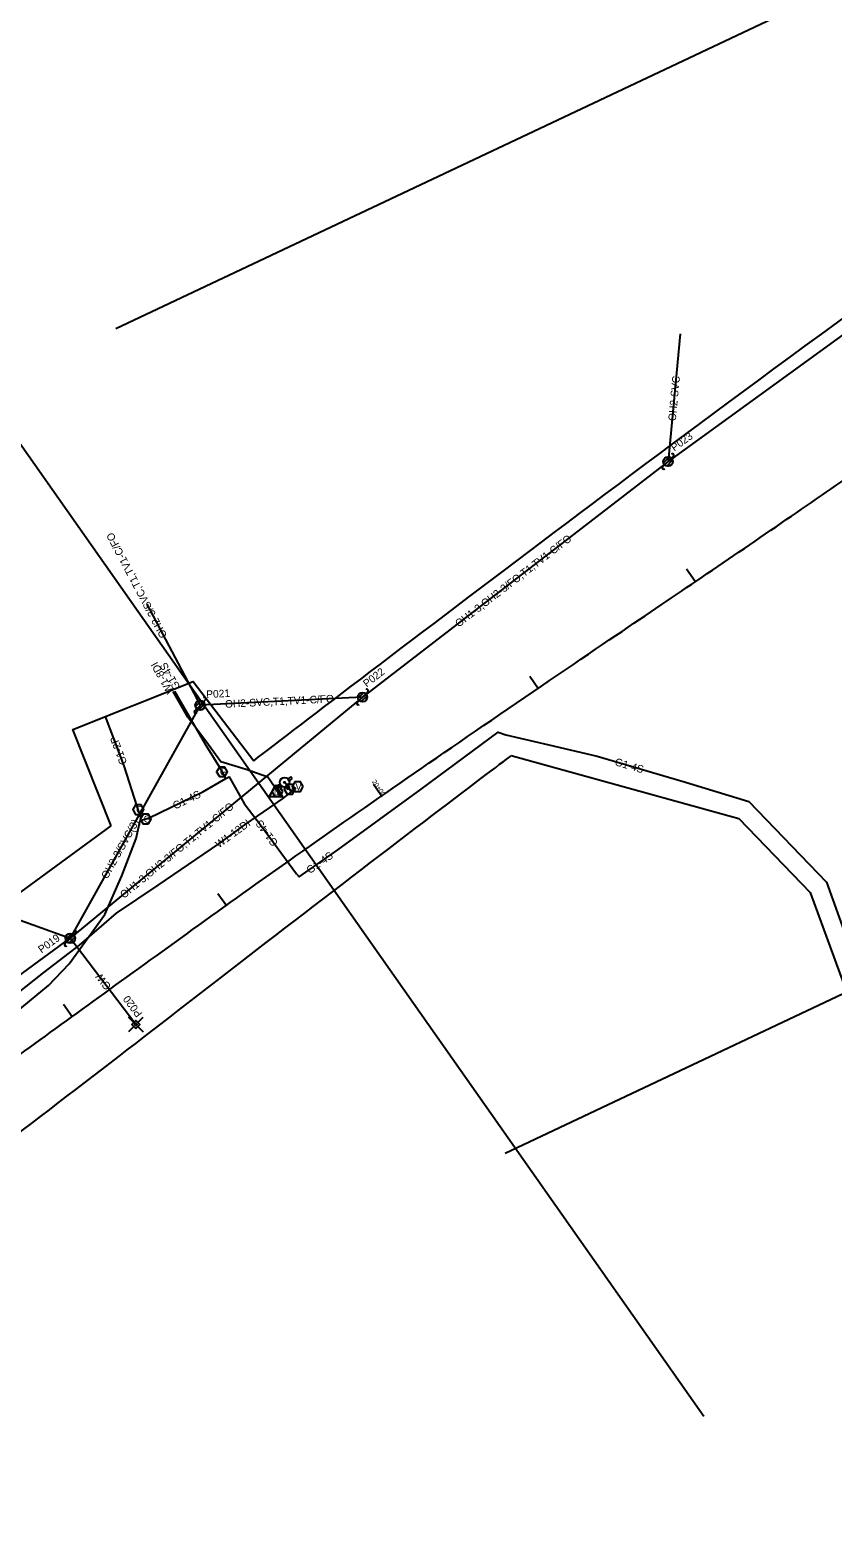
# Model space of a CAD drawing. Extents: x 1991878 to 2008544, y 770238 to 1141211.
# Drawn here: x 2004550 to 2004972, y 1139018 to 1139811 of the extents above; entities that cross this region are included whole.
import ezdxf

# ---------------------------------------------------------------- set-up
doc = ezdxf.new("R2010")
doc.units = 0
for name, color, linetype in [('RD_EX_SU_Gas', 7, 'Continuous'), ('RD_EX_SU_H2O', 7, 'Continuous'), ('RD_EX_SU_Misc', 7, 'Continuous'), ('RD_EX_SU_Ovhd', 7, 'Continuous'), ('RD_EX_SU_Pole', 7, 'Continuous'), ('RD_EX_SU_SwpLmt', 7, 'Continuous'), ('RD_EX_SU_TX_Gas', 7, 'Continuous'), ('RD_EX_SU_TX_H2O', 7, 'Continuous'), ('RD_EX_SU_TX_Ovhd', 7, 'Continuous'), ('RD_EX_SU_TX_Pole', 7, 'Continuous'), ('RD_HC_Cl', 7, 'Continuous')]:
    doc.layers.add(name, color=color, linetype=linetype)

msp = doc.modelspace()

# ---------------------------------------------------------------- linework, layer by layer
at = {"layer": 'RD_EX_SU_Gas'}
for points in [[(2004127.39, 1138992.43), (2004167.83, 1139021.75), (2004208.7, 1139051.33), (2004249.23, 1139080.61), (2004289.2, 1139109.77), (2004329.8, 1139139.24), (2004370.29, 1139168.18), (2004410.8, 1139197.77), (2004451.13, 1139226.8), (2004491.65, 1139256.41), (2004532.34, 1139286.17), (2004559.51, 1139308.55), (2004570.45, 1139319.96), (2004589.25, 1139345.84), (2004598.18, 1139366.3), (2004605.75, 1139385.94), (2004607.89, 1139395.38), (2004612.64, 1139396.79), (2004640.85, 1139410.39), (2004653.01, 1139417.54), (2004650.63, 1139421.79), (2004642.64, 1139434.89), (2004626.13, 1139463.52)], [(2004608.45, 1139396.57), (2004606.18, 1139402.73), (2004599.47, 1139424.1), (2004589.65, 1139450.12)], [(2004653.01, 1139417.54), (2004654.65, 1139418.3), (2004662.64, 1139404.34), (2004671.73, 1139392.42), (2004690.15, 1139367.32), (2004691.56, 1139365.69), (2004711.89, 1139379.94), (2004755.77, 1139411.93), (2004796.21, 1139441.85), (2004800.33, 1139440.53), (2004823.01, 1139435.16), (2004848.41, 1139429.24), (2004894.92, 1139415.6), (2004928.18, 1139405.32), (2004969.16, 1139362.83), (2004982.49, 1139325.73), (2004996.03, 1139288.62), (2005016.28, 1139234.18), (2005017.5, 1139230.57)]]:
    msp.add_lwpolyline(points, dxfattribs=at)
for points in [[(2004652.4, 1139418.48), (2004653.84, 1139420.98), (2004652.4, 1139423.48), (2004649.51, 1139423.48), (2004648.07, 1139420.98), (2004649.51, 1139418.48)], [(2004608.33, 1139398.59), (2004609.77, 1139401.09), (2004608.33, 1139403.59), (2004605.44, 1139403.59), (2004604, 1139401.09), (2004605.44, 1139398.59)], [(2004612.24, 1139393.64), (2004613.68, 1139396.14), (2004612.24, 1139398.64), (2004609.35, 1139398.64), (2004607.91, 1139396.14), (2004609.35, 1139393.64)]]:
    msp.add_lwpolyline(points, close=True, dxfattribs=at)
at = {"layer": 'RD_EX_SU_H2O'}
for p, q in [((2004687.17, 1139418.36), (2004685.58, 1139417.29)), ((2004686.24, 1139416.22), (2004687.87, 1139417.31)), ((2004687.87, 1139417.31), (2004687.17, 1139418.36)), ((2004681.49, 1139414.54), (2004679.85, 1139413.44)), ((2004679.85, 1139413.44), (2004680.55, 1139412.39)), ((2004680.55, 1139412.39), (2004682.24, 1139413.52)), ((2004684.62, 1139413.08), (2004685.53, 1139411.72)), ((2004685.53, 1139411.72), (2004686.58, 1139412.42)), ((2004686.58, 1139412.42), (2004685.68, 1139413.76))]:
    msp.add_line(p, q, dxfattribs=at)
for points in [[(2004682.25, 1139407.48), (2004678.5, 1139413.01), (2004675.07, 1139418.12), (2004663.58, 1139422.21), (2004650.35, 1139426.3), (2004643.87, 1139435.2), (2004632.85, 1139449.76), (2004625.26, 1139463.35)], [(2004687.51, 1139410.38), (2004687.09, 1139410.94), (2004684.47, 1139414.6), (2004683.84, 1139415.47)], [(2004122.45, 1139000.61), (2004162.73, 1139029.52), (2004204.05, 1139057.78), (2004245.07, 1139087.18), (2004285.23, 1139114.51), (2004311.58, 1139134.01), (2004333.1, 1139148.87), (2004366.63, 1139172.54), (2004408.38, 1139201.91), (2004448.87, 1139231.66), (2004488.17, 1139261.92), (2004511.05, 1139279.96), (2004528.13, 1139292.48), (2004557.12, 1139315.44), (2004575.83, 1139329.69), (2004595.34, 1139346.68), (2004617.3, 1139361.37), (2004649.17, 1139383.17), (2004663.69, 1139393.7), (2004675.95, 1139402.09), (2004682.78, 1139406.85), (2004687.52, 1139410.39), (2004690.03, 1139412.66)]]:
    msp.add_lwpolyline(points, dxfattribs=at)
for points in [[(2004693.63, 1139413.18), (2004692.18, 1139415.68), (2004689.3, 1139415.68), (2004687.85, 1139413.18), (2004689.3, 1139410.68), (2004692.18, 1139410.68)], [(2004682.93, 1139410.72), (2004681.49, 1139413.22), (2004678.6, 1139413.22), (2004677.16, 1139410.72), (2004678.6, 1139408.22), (2004681.49, 1139408.22)], [(2004689.46, 1139411.81), (2004688.01, 1139414.31), (2004685.13, 1139414.31), (2004683.68, 1139411.81), (2004685.13, 1139409.31), (2004688.01, 1139409.31)]]:
    msp.add_lwpolyline(points, close=True, dxfattribs=at)
for radius in [2.52, 0.315]:
    msp.add_circle((2004683.84, 1139415.47), radius, dxfattribs=at)
for start, end in [(17.25412, 46.23044), (201.60041, 230.57673), (288.16095, 317.12819)]:
    msp.add_arc((2004683.84, 1139415.47), 2.52, start, end, dxfattribs=at)
at = {"layer": 'RD_EX_SU_Misc'}
msp.add_lwpolyline([(2004679.21, 1139413.96), (2004675.75, 1139407.96), (2004682.68, 1139407.96)], close=True, dxfattribs=at)
at = {"layer": 'RD_EX_SU_Ovhd'}
for p, q in [((2005150.23, 1139776.39), (2004885.7, 1139584.32)), ((2004892.13, 1139651.48), (2004885.7, 1139584.32)), ((2004885.7, 1139584.32), (2004724.89, 1139460.33)), ((2004611.37, 1139509.16), (2004639.37, 1139455.99)), ((2004724.89, 1139460.33), (2004571.07, 1139333.35)), ((2004639.37, 1139455.99), (2004571.07, 1139333.35)), ((2004724.89, 1139460.33), (2004639.37, 1139455.99)), ((2004528.25, 1139348.79), (2004571.07, 1139333.35)), ((2004444.61, 1139241.4), (2004571.07, 1139333.35)), ((2004605.55, 1139287.94), (2004571.07, 1139333.35))]:
    msp.add_line(p, q, dxfattribs=at)
at = {"layer": 'RD_EX_SU_Pole'}
for p, q in [((2004882.87, 1139581.49), (2004883.93, 1139582.55)), ((2004883.28, 1139583.67), (2004886.34, 1139586.74)), ((2004883.93, 1139582.55), (2004887.46, 1139586.09)), ((2004885.05, 1139581.91), (2004888.11, 1139584.97)), ((2004887.46, 1139586.09), (2004888.52, 1139587.15)), ((2004722.47, 1139459.68), (2004725.53, 1139462.75)), ((2004726.65, 1139462.1), (2004727.71, 1139463.16)), ((2004636.96, 1139455.34), (2004640.02, 1139458.4)), ((2004637.6, 1139454.22), (2004641.14, 1139457.75)), ((2004638.72, 1139453.57), (2004641.78, 1139456.63)), ((2004641.14, 1139457.75), (2004642.2, 1139458.81)), ((2004722.06, 1139457.5), (2004723.12, 1139458.56)), ((2004723.12, 1139458.56), (2004726.65, 1139462.1)), ((2004724.24, 1139457.92), (2004727.3, 1139460.98)), ((2004636.54, 1139453.16), (2004637.6, 1139454.22)), ((2004568.65, 1139332.71), (2004571.71, 1139335.77)), ((2004572.84, 1139335.12), (2004573.9, 1139336.18)), ((2004568.24, 1139330.53), (2004569.3, 1139331.59)), ((2004569.3, 1139331.59), (2004572.84, 1139335.12)), ((2004570.42, 1139330.94), (2004573.48, 1139334)), ((2004604.49, 1139289), (2004601.66, 1139291.83)), ((2004606.58, 1139289.06), (2004609.41, 1139291.9)), ((2004604.44, 1139286.9), (2004601.61, 1139284.07)), ((2004606.61, 1139286.88), (2004609.44, 1139284.05))]:
    msp.add_line(p, q, dxfattribs=at)
for points in [[(2004605.55, 1139285.82), (2004607.67, 1139287.94), (2004605.55, 1139290.06), (2004603.43, 1139287.94)], [(2004605.55, 1139287.23), (2004606.26, 1139287.94), (2004605.55, 1139288.65), (2004604.84, 1139287.94)]]:
    msp.add_lwpolyline(points, close=True, dxfattribs=at)
for centre in [(2004885.7, 1139584.32), (2004724.89, 1139460.33), (2004639.37, 1139455.99), (2004571.07, 1139333.35)]:
    msp.add_circle(centre, 2.5, dxfattribs=at)
for centre, start, end in [((2004883.4, 1139580.96), 135.01158, 315.01158), ((2004887.99, 1139587.68), 315.01158, 135.01158), ((2004727.18, 1139463.69), 315.01158, 135.01158), ((2004641.67, 1139459.35), 315.01158, 135.01158), ((2004722.59, 1139456.97), 135.01158, 315.01158), ((2004637.07, 1139452.63), 135.01158, 315.01158), ((2004573.37, 1139336.71), 315.01158, 135.01158), ((2004568.77, 1139329.99), 135.01158, 315.01158)]:
    msp.add_arc(centre, 0.75, start, end, dxfattribs=at)
at = {"layer": 'RD_EX_SU_SwpLmt'}
msp.add_line((2004357.93, 1139220.65), (2004592.56, 1139392.56), dxfattribs=at)
for points in [[(2004592.56, 1139392.56), (2004572.36, 1139443.22), (2004635.75, 1139468.5), (2004667.64, 1139426.86)], [(2004803.15, 1139429.56), (2004922.88, 1139396.41), (2004960.5, 1139357.41), (2005010.51, 1139221)]]:
    msp.add_lwpolyline(points, dxfattribs=at)
for points in [[(2004667.64, 1139426.86), (2004691.38, 1139445.04), (2004818.69, 1139542.26), (2004974.3, 1139658.1), (2005093.47, 1139743.03)], [(2004394.78, 1139119.65), (2004422.38, 1139139.88), (2004545.39, 1139230.86), (2004674.47, 1139331.94), (2004798.6, 1139426.11), (2004803.15, 1139429.56)]]:
    msp.add_open_spline(points, degree=3, dxfattribs=at)
msp.add_spline([(2004394.78, 1139119.65), (2004440.28, 1138994.6), (2004535.99, 1138728.08), (2004687.71, 1138314.66), (2004781.55, 1138057.24), (2005017.8, 1137400.02), (2005029.38, 1137367.89)], degree=3, dxfattribs=at)
at = {"layer": 'RD_HC_Cl'}
for p, q in [((2005303.45, 1139988.79), (2004595.02, 1139654.18)), ((2004485.41, 1139677.79), (2004904.59, 1139081.9)), ((2005508.45, 1139554.76), (2004800.02, 1139220.15)), ((2004895.41, 1139527.89), (2004899.94, 1139521.29)), ((2004812.94, 1139471.33), (2004817.47, 1139464.74)), ((2004730.59, 1139414.51), (2004735.16, 1139407.94)), ((2004648.74, 1139356.92), (2004653.37, 1139350.4)), ((2004567.43, 1139298.61), (2004572.11, 1139292.12))]:
    msp.add_line(p, q, dxfattribs=at)
msp.add_open_spline([(2002937.27, 1138556.06), (2003081.12, 1138596.24), (2003224.54, 1138636.27), (2003324.8, 1138664.72), (2003440.8, 1138697.76), (2003610.3, 1138743.13), (2003753.45, 1138782.34), (2003851.96, 1138815.09), (2003945.32, 1138855.48), (2004023.07, 1138899.74), (2004117.46, 1138962.96), (2004239.69, 1139051.13), (2004401.3, 1139168.16), (2004522.74, 1139256.47), (2004724.1, 1139402.13), (2005003.72, 1139590.96), (2005189.76, 1139724.82), (2005285.27, 1139787.25)], degree=2, dxfattribs=at)

# ---------------------------------------------------------------- texts
at = {"layer": 'RD_EX_SU_Gas'}
for p in [(2004649.8, 1139419.11), (2004605.74, 1139399.22), (2004609.64, 1139394.27)]:
    msp.add_text('G', height=3.75, dxfattribs=at).set_placement(p)
at = {"layer": 'RD_EX_SU_H2O'}
for p in [(2004689.53, 1139411.31), (2004678.84, 1139408.85), (2004685.36, 1139409.94)]:
    msp.add_text('V', height=3.75, dxfattribs=at).set_placement(p)
at = {"layer": 'RD_EX_SU_Misc'}
msp.add_text('U', height=2.4, dxfattribs=at).set_placement((2004678.46, 1139408.76))
at = {"layer": 'RD_EX_SU_TX_Gas'}
for s, rotation, p in [('G1-4S', 119.98024, (2004629.15, 1139465.57)), ('G1-2P', 110.67002, (2004601.05, 1139425.63)), ('G1-4S', 343.65218, (2004857.34, 1139424.53)), ('G1-4S', 25.73098, (2004626.23, 1139401.1)), ('G1-4S', 126.28023, (2004680.7, 1139383.59)), ('G1-4S', 35.03698, (2004697.15, 1139367.13))]:
    msp.add_text(s, height=4, rotation=rotation, dxfattribs=at).set_placement(p)
at = {"layer": 'RD_EX_SU_TX_H2O'}
for s, rotation, p in [('W1-8DI', 119.16984, (2004625.56, 1139463.44)), ('W1-12DI', 35.94844, (2004649.2, 1139380.69))]:
    msp.add_text(s, height=4, rotation=rotation, dxfattribs=at).set_placement(p)
at = {"layer": 'RD_EX_SU_TX_Ovhd'}
for s, rotation, p in [('OH2-SVC', 84.52588, (2004889.74, 1139605.51)), ('OH2-3/SVC,T1,TV1-C/FO', 117.76744, (2004622.17, 1139492.66)), ('OH1-3,OH2-3/FO,T1,TV1-C/FO', 37.63328, (2004775.56, 1139496.87)), ('OH2-SVC,T1,TV1-C/FO', 2.90932, (2004652.6, 1139454.66)), ('OH1-3,OH2-3/FO,T1,TV1-C/FO', 39.53995, (2004599.32, 1139354.08)), ('OH2-3/SVC(3)', 60.88363, (2004590.57, 1139364.26)), ('GW', 127.21013, (2004592.82, 1139308.02))]:
    msp.add_text(s, height=4, rotation=rotation, dxfattribs=at).set_placement(p)
at = {"layer": 'RD_EX_SU_TX_Pole'}
for s, rotation, p in [('P023', 35.98238, (2004889.03, 1139589.51)), ('P022', 37.63328, (2004727.08, 1139465.28)), ('P021', 2.90932, (2004642.72, 1139459.79)), ('P019', 36.02096, (2004555.92, 1139325.33)), ('P020', 127.21013, (2004609.21, 1139293.75))]:
    msp.add_text(s, height=4, rotation=rotation, dxfattribs=at).set_placement(p)
at = {"layer": 'RD_HC_Cl'}
msp.add_text('20+00', height=2.5, rotation=304.83264, dxfattribs=at).set_placement((2004729.7, 1139415.79))

doc.saveas('drawing.dxf')
